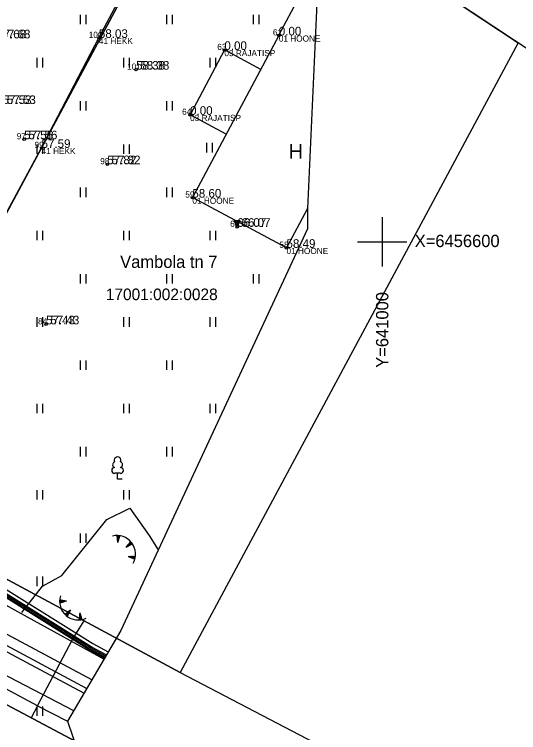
# Model space of a CAD drawing. Extents: x 640891 to 641083, y 6456526 to 6456669.
# Drawn here: x 640970.2 to 641011.1, y 6456560.3 to 6456618.4 of the extents above; entities that cross this region are included whole.
import ezdxf

# ---------------------------------------------------------------- set-up
doc = ezdxf.new("R2010")
doc.units = 0
for name, color, linetype in [('100koma2', 7, 'Continuous'), ('HALJASTUS', 7, 'Continuous'), ('HOONE', 7, 'Continuous'), ('KORGUS', 7, 'Continuous'), ('KPKAABEL', 7, 'Continuous'), ('KTRASS', 7, 'Continuous'), ('MOOTKORG', 7, 'Continuous'), ('MOOTKORG_MUU', 7, 'Continuous'), ('MOOTMPUNKT', 7, 'Continuous'), ('MOOTNR', 7, 'Continuous'), ('MOOTPIIR', 7, 'Continuous'), ('MPKAABEL', 7, 'Continuous'), ('PIIR', 7, 'Continuous'), ('PUU', 7, 'Continuous'), ('RELJEEF', 7, 'Continuous'), ('SITRASS', 7, 'Continuous'), ('SKTRASS', 7, 'Continuous'), ('TEE', 7, 'Continuous'), ('VORK', 7, 'Continuous'), ('VTRASS', 7, 'Continuous')]:
    doc.layers.add(name, color=color, linetype=linetype)

msp = doc.modelspace()

# ---------------------------------------------------------------- linework, layer by layer
at = {"layer": 'HALJASTUS'}
for p, q in [((640975.545, 6456618.381), (640975.545, 6456617.619)), ((640976, 6456618.381), (640976, 6456617.619)), ((640982.545, 6456618.381), (640982.545, 6456617.619)), ((640983, 6456618.381), (640983, 6456617.619)), ((640989.545, 6456618.381), (640989.545, 6456617.619)), ((640990, 6456618.381), (640990, 6456617.619)), ((640972.045, 6456614.881), (640972.045, 6456614.119)), ((640972.5, 6456614.881), (640972.5, 6456614.119)), ((640979.045, 6456614.881), (640979.045, 6456614.119)), ((640979.5, 6456614.881), (640979.5, 6456614.119)), ((640986.045, 6456614.881), (640986.045, 6456614.119)), ((640986.5, 6456614.881), (640986.5, 6456614.119)), ((640975.545, 6456611.381), (640975.545, 6456610.619)), ((640976, 6456611.381), (640976, 6456610.619)), ((640982.545, 6456611.381), (640982.545, 6456610.619)), ((640983, 6456611.381), (640983, 6456610.619)), ((640972.045, 6456607.881), (640972.045, 6456607.119)), ((640972.5, 6456607.881), (640972.5, 6456607.119)), ((640979.045, 6456607.881), (640979.045, 6456607.119)), ((640979.5, 6456607.881), (640979.5, 6456607.119)), ((640985.78, 6456607.996), (640985.78, 6456607.235)), ((640986.236, 6456607.996), (640986.236, 6456607.235)), ((640975.545, 6456604.381), (640975.545, 6456603.619)), ((640976, 6456604.381), (640976, 6456603.619)), ((640982.545, 6456604.381), (640982.545, 6456603.619)), ((640983, 6456604.381), (640983, 6456603.619)), ((640972.045, 6456600.881), (640972.045, 6456600.119)), ((640972.5, 6456600.881), (640972.5, 6456600.119)), ((640979.045, 6456600.881), (640979.045, 6456600.119)), ((640979.5, 6456600.881), (640979.5, 6456600.119)), ((640986.045, 6456600.881), (640986.045, 6456600.119)), ((640986.5, 6456600.881), (640986.5, 6456600.119)), ((640975.545, 6456597.381), (640975.545, 6456596.619)), ((640976, 6456597.381), (640976, 6456596.619)), ((640982.545, 6456597.381), (640982.545, 6456596.619)), ((640983, 6456597.381), (640983, 6456596.619)), ((640989.545, 6456597.381), (640989.545, 6456596.619)), ((640990, 6456597.381), (640990, 6456596.619)), ((640972.045, 6456593.881), (640972.045, 6456593.119)), ((640972.5, 6456593.881), (640972.5, 6456593.119)), ((640979.045, 6456593.881), (640979.045, 6456593.119)), ((640979.5, 6456593.881), (640979.5, 6456593.119)), ((640986.045, 6456593.881), (640986.045, 6456593.119)), ((640986.5, 6456593.881), (640986.5, 6456593.119)), ((640975.545, 6456590.381), (640975.545, 6456589.619)), ((640976, 6456590.381), (640976, 6456589.619)), ((640982.545, 6456590.381), (640982.545, 6456589.619)), ((640983, 6456590.381), (640983, 6456589.619)), ((640972.045, 6456586.881), (640972.045, 6456586.119)), ((640972.5, 6456586.881), (640972.5, 6456586.119)), ((640979.045, 6456586.881), (640979.045, 6456586.119)), ((640979.5, 6456586.881), (640979.5, 6456586.119)), ((640986.045, 6456586.881), (640986.045, 6456586.119)), ((640986.5, 6456586.881), (640986.5, 6456586.119)), ((640975.545, 6456583.381), (640975.545, 6456582.619)), ((640976, 6456583.381), (640976, 6456582.619)), ((640982.545, 6456583.381), (640982.545, 6456582.619)), ((640983, 6456583.381), (640983, 6456582.619)), ((640972.045, 6456579.881), (640972.045, 6456579.119)), ((640972.5, 6456579.881), (640972.5, 6456579.119)), ((640979.045, 6456579.881), (640979.045, 6456579.119)), ((640979.5, 6456579.881), (640979.5, 6456579.119)), ((640975.545, 6456576.381), (640975.545, 6456575.619)), ((640976, 6456576.381), (640976, 6456575.619)), ((640972.045, 6456572.881), (640972.045, 6456572.119)), ((640972.5, 6456572.881), (640972.5, 6456572.119)), ((640972.045, 6456562.381), (640972.045, 6456561.619)), ((640972.5, 6456562.381), (640972.5, 6456561.619))]:
    msp.add_line(p, q, dxfattribs=at)
for points in [[(640962.925, 6456576.62), (640957.383, 6456579.521), (640966.138, 6456596.056), (640972.417, 6456607.592), (640977.059, 6456616.501), (640985.041, 6456631.518)], [(640970.815, 6456569.988), (640972.5, 6456572.119), (640974.047, 6456572.963), (640977.712, 6456577.496), (640979.559, 6456578.42), (640981.117, 6456576.226), (640981.868, 6456575.042)]]:
    msp.add_lwpolyline(points, dxfattribs=at)
at = {"layer": 'HOONE'}
for p, q in [((640993.648, 6456620.522), (640991.616, 6456616.709)), ((640991.628, 6456616.702), (640984.629, 6456603.57)), ((640991.616, 6456616.709), (640991.628, 6456616.702)), ((640990.165, 6456613.956), (640987.221, 6456615.525)), ((640987.37, 6456608.714), (640984.444, 6456610.273)), ((640992.253, 6456599.507), (640984.629, 6456603.57)), ((640993.953, 6456602.696), (640992.253, 6456599.507))]:
    msp.add_line(p, q, dxfattribs=at)
msp.add_lwpolyline([(640987.221, 6456615.525), (640984.444, 6456610.273)], dxfattribs=at)
at = {"layer": 'KORGUS'}
for p, q in [((640988.261, 6456601.203), (640988.014, 6456601.69)), ((640988.507, 6456601.69), (640988.014, 6456601.69)), ((640988.042, 6456601.69), (640988.378, 6456601.435)), ((640988.083, 6456601.69), (640988.389, 6456601.457)), ((640988.125, 6456601.69), (640988.401, 6456601.48)), ((640988.166, 6456601.69), (640988.412, 6456601.503)), ((640988.207, 6456601.69), (640988.424, 6456601.525)), ((640988.248, 6456601.69), (640988.435, 6456601.548)), ((640988.261, 6456601.203), (640988.507, 6456601.69)), ((640988.29, 6456601.69), (640988.447, 6456601.571)), ((640988.331, 6456601.69), (640988.458, 6456601.593)), ((640988.372, 6456601.69), (640988.47, 6456601.616)), ((640988.413, 6456601.69), (640988.481, 6456601.639)), ((640988.455, 6456601.69), (640988.493, 6456601.661)), ((640988.496, 6456601.69), (640988.504, 6456601.684)), ((640988.023, 6456601.674), (640988.366, 6456601.412)), ((640988.049, 6456601.623), (640988.355, 6456601.389)), ((640988.074, 6456601.571), (640988.343, 6456601.367)), ((640988.1, 6456601.52), (640988.332, 6456601.344)), ((640988.126, 6456601.469), (640988.32, 6456601.321)), ((640988.152, 6456601.418), (640988.309, 6456601.299)), ((640988.178, 6456601.367), (640988.297, 6456601.276)), ((640988.204, 6456601.316), (640988.286, 6456601.253)), ((640988.23, 6456601.265), (640988.274, 6456601.23)), ((640988.256, 6456601.213), (640988.263, 6456601.208))]:
    msp.add_line(p, q, dxfattribs=at)
for centre in [(640980.07, 6456613.931), (640971.005, 6456608.294), (640977.739, 6456606.273), (640972.781, 6456593.308)]:
    msp.add_circle(centre, 0.1, dxfattribs=at)
at = {"layer": 'KPKAABEL'}
msp.add_lwpolyline([(640977.507, 6456566.281), (640976.27, 6456566.95), (640967.49, 6456572.43), (640959.27, 6456576.625), (640951.05, 6456580.82), (640939.86, 6456586.9), (640935.075, 6456589.63), (640930.29, 6456592.36), (640924.23, 6456595.65), (640919.26, 6456598.135), (640914.117, 6456600.706)], dxfattribs=at)
at = {"layer": 'KTRASS'}
msp.add_lwpolyline([(640976.059, 6456563.819), (640955.081, 6456575.091)], dxfattribs=at)
at = {"layer": 'MOOTMPUNKT'}
for centre in [(640977.059, 6456616.501), (640991.628, 6456616.702), (640987.221, 6456615.525), (640980.07, 6456613.931), (640984.444, 6456610.273), (640971.005, 6456608.294), (640972.417, 6456607.592), (640977.739, 6456606.273), (640984.629, 6456603.57), (640988.261, 6456601.203), (640992.252, 6456599.504), (640972.781, 6456593.308)]:
    msp.add_circle(centre, 0.1, dxfattribs=at)
at = {"layer": 'MOOTPIIR'}
msp.add_lwpolyline([(640994.744, 6456619.938), (640993.953, 6456602.696), (640993.953, 6456601.05), (640978.828, 6456568.525), (640974.506, 6456561.178), (640980.174, 6456544.523), (640977.11, 6456538.585), (640976.662, 6456538.007), (640959.29, 6456546.142)], dxfattribs=at)
at = {"layer": 'MPKAABEL'}
for points in [[(640914.173, 6456600.793), (640919.31, 6456598.225), (640924.28, 6456595.74), (640927.31, 6456594.095), (640930.34, 6456592.45), (640935.125, 6456589.72), (640939.91, 6456586.99), (640945.495, 6456583.945), (640951.08, 6456580.9), (640959.31, 6456576.71), (640967.54, 6456572.52), (640971.93, 6456569.78), (640976.32, 6456567.04), (640977.56, 6456566.369)], [(640977.608, 6456566.451), (640976.37, 6456567.12), (640971.98, 6456569.865), (640967.59, 6456572.61), (640959.355, 6456576.785), (640951.12, 6456580.96), (640945.54, 6456584.015), (640939.96, 6456587.07), (640935.175, 6456589.8), (640930.39, 6456592.53), (640927.355, 6456594.18), (640924.32, 6456595.83), (640919.35, 6456598.315), (640914.227, 6456600.876)], [(640977.66, 6456566.54), (640976.42, 6456567.21), (640972.03, 6456569.95), (640967.64, 6456572.69), (640959.395, 6456576.855), (640951.15, 6456581.02), (640945.58, 6456584.09), (640940.01, 6456587.16), (640935.225, 6456589.89), (640930.44, 6456592.62), (640927.405, 6456594.27), (640924.37, 6456595.92), (640919.4, 6456598.405), (640914.283, 6456600.963)], [(640957.06, 6456579.17), (640956.96, 6456578.31), (640962.37, 6456575.635), (640967.78, 6456572.96), (640976.57, 6456567.48), (640977.808, 6456566.792)]]:
    msp.add_lwpolyline(points, dxfattribs=at)
at = {"layer": 'PIIR'}
for points in [[(641029.209, 6456604.07), (641000.58, 6456623), (641039.59, 6456660.086)], [(640890.598, 6456615.08), (640904.36, 6456607.7), (640930.79, 6456593.51), (640957.22, 6456579.32), (640983.63, 6456565.13), (641002.905, 6456555.058)], [(640993.023, 6456550.09), (640989.66, 6456551.83), (640963.18, 6456565.91), (640936.74, 6456580.1), (640910.31, 6456594.28), (640890.598, 6456604.875)], [(640941.583, 6456525.865), (640963.18, 6456565.91), (640989.66, 6456551.83), (640975.643, 6456525.865)]]:
    msp.add_lwpolyline(points, dxfattribs=at)
for points in [[(640957.22, 6456579.32), (640930.79, 6456593.51), (640960.76, 6456649.34), (640985.89, 6456632.73)], [(640983.63, 6456565.13), (640957.22, 6456579.32), (640985.89, 6456632.73), (641000.58, 6456623), (641011.01, 6456616.1)]]:
    msp.add_lwpolyline(points, close=True, dxfattribs=at)
at = {"layer": 'PUU'}
for p, q in [((640978.811, 6456581.248), (640978.331, 6456581.248)), ((640978.571, 6456580.773), (640978.571, 6456581.248)), ((640978.951, 6456580.773), (640978.571, 6456580.773))]:
    msp.add_line(p, q, dxfattribs=at)
for centre, radius, start, end in [((640978.571, 6456582.293), 0.277, 332.5799, 207.4201), ((640978.401, 6456581.945), 0.233, 109.02174, 253.14154), ((640978.741, 6456581.945), 0.233, 286.85082, 70.98591), ((640978.334, 6456581.485), 0.238, 90.0016, 269.3953), ((640978.809, 6456581.485), 0.238, 270.6047, 89.9984)]:
    msp.add_arc(centre, radius, start, end, dxfattribs=at)
at = {"layer": 'RELJEEF'}
for p, q in [((640978.592, 6456575.65), (640978.533, 6456576.213)), ((640978.534, 6456576.203), (640978.685, 6456575.974)), ((640978.539, 6456576.149), (640978.676, 6456575.943)), ((640978.545, 6456576.095), (640978.667, 6456575.911)), ((640978.557, 6456576.213), (640978.694, 6456576.006)), ((640978.588, 6456576.211), (640978.703, 6456576.037)), ((640978.592, 6456575.65), (640978.749, 6456576.194)), ((640978.619, 6456576.209), (640978.713, 6456576.069)), ((640978.651, 6456576.207), (640978.722, 6456576.101)), ((640978.683, 6456576.203), (640978.731, 6456576.132)), ((640978.716, 6456576.199), (640978.74, 6456576.164)), ((640978.551, 6456576.042), (640978.658, 6456575.88)), ((640978.556, 6456575.988), (640978.649, 6456575.848)), ((640978.562, 6456575.934), (640978.64, 6456575.817)), ((640978.568, 6456575.88), (640978.631, 6456575.785)), ((640978.573, 6456575.827), (640978.622, 6456575.754)), ((640978.579, 6456575.773), (640978.613, 6456575.722)), ((640978.585, 6456575.719), (640978.604, 6456575.69)), ((640979.263, 6456575.281), (640979.637, 6456575.706)), ((640979.263, 6456575.281), (640979.77, 6456575.535)), ((640979.488, 6456575.536), (640979.448, 6456575.374)), ((640979.523, 6456575.577), (640979.477, 6456575.388)), ((640979.559, 6456575.617), (640979.507, 6456575.403)), ((640979.595, 6456575.658), (640979.536, 6456575.418)), ((640979.63, 6456575.699), (640979.565, 6456575.432)), ((640979.654, 6456575.688), (640979.595, 6456575.447)), ((640979.674, 6456575.664), (640979.624, 6456575.462)), ((640979.693, 6456575.64), (640979.653, 6456575.477)), ((640979.713, 6456575.615), (640979.683, 6456575.491)), ((640979.732, 6456575.589), (640979.712, 6456575.506)), ((640979.751, 6456575.562), (640979.741, 6456575.521)), ((640979.309, 6456575.334), (640979.301, 6456575.3)), ((640979.345, 6456575.374), (640979.33, 6456575.315)), ((640979.381, 6456575.415), (640979.36, 6456575.329)), ((640979.416, 6456575.455), (640979.389, 6456575.344)), ((640979.452, 6456575.496), (640979.419, 6456575.359)), ((640979.441, 6456574.508), (640979.964, 6456574.29)), ((640979.441, 6456574.508), (640980.008, 6456574.502)), ((640979.511, 6456574.507), (640979.48, 6456574.492)), ((640979.565, 6456574.507), (640979.511, 6456574.479)), ((640979.619, 6456574.506), (640979.541, 6456574.467)), ((640979.673, 6456574.506), (640979.571, 6456574.454)), ((640979.727, 6456574.505), (640979.602, 6456574.441)), ((640979.781, 6456574.504), (640979.632, 6456574.429)), ((640979.835, 6456574.504), (640979.662, 6456574.416)), ((640979.889, 6456574.503), (640979.692, 6456574.403)), ((640979.943, 6456574.503), (640979.723, 6456574.391)), ((640979.997, 6456574.502), (640979.753, 6456574.378)), ((640980.004, 6456574.477), (640979.783, 6456574.365)), ((640980, 6456574.447), (640979.814, 6456574.353)), ((640979.994, 6456574.416), (640979.844, 6456574.34)), ((640979.988, 6456574.385), (640979.874, 6456574.327)), ((640979.981, 6456574.353), (640979.904, 6456574.315)), ((640979.973, 6456574.321), (640979.935, 6456574.302)), ((640973.877, 6456570.894), (640973.977, 6456570.973)), ((640973.877, 6456570.862), (640974.009, 6456570.967)), ((640973.878, 6456570.926), (640973.945, 6456570.98)), ((640973.878, 6456570.831), (640974.041, 6456570.961)), ((640973.879, 6456570.959), (640973.912, 6456570.986)), ((640973.88, 6456570.8), (640974.073, 6456570.955)), ((640974.438, 6456570.884), (640973.881, 6456570.992)), ((640974.438, 6456570.884), (640973.881, 6456570.775)), ((640973.892, 6456570.777), (640974.106, 6456570.948)), ((640973.945, 6456570.788), (640974.138, 6456570.942)), ((640973.998, 6456570.798), (640974.17, 6456570.936)), ((640974.051, 6456570.808), (640974.202, 6456570.93)), ((640974.104, 6456570.819), (640974.235, 6456570.924)), ((640974.157, 6456570.829), (640974.267, 6456570.917)), ((640974.21, 6456570.84), (640974.299, 6456570.911)), ((640974.263, 6456570.85), (640974.331, 6456570.905)), ((640974.316, 6456570.86), (640974.363, 6456570.899)), ((640974.369, 6456570.871), (640974.396, 6456570.892)), ((640974.769, 6456570.164), (640974.325, 6456569.812)), ((640974.349, 6456569.789), (640974.35, 6456569.832)), ((640974.373, 6456569.767), (640974.376, 6456569.852)), ((640974.397, 6456569.745), (640974.402, 6456569.873)), ((640974.421, 6456569.725), (640974.427, 6456569.893)), ((640974.446, 6456569.705), (640974.453, 6456569.914)), ((640974.47, 6456569.686), (640974.479, 6456569.934)), ((640974.769, 6456570.164), (640974.49, 6456569.671)), ((640974.495, 6456569.68), (640974.504, 6456569.954)), ((640974.522, 6456569.727), (640974.53, 6456569.975)), ((640974.548, 6456569.774), (640974.556, 6456569.995)), ((640974.575, 6456569.821), (640974.582, 6456570.015)), ((640974.602, 6456569.868), (640974.607, 6456570.036)), ((640974.628, 6456569.915), (640974.633, 6456570.056)), ((640974.655, 6456569.962), (640974.659, 6456570.077)), ((640974.682, 6456570.009), (640974.685, 6456570.097)), ((640974.708, 6456570.056), (640974.71, 6456570.117)), ((640974.735, 6456570.103), (640974.736, 6456570.138)), ((640975.502, 6456569.94), (640975.459, 6456569.375)), ((640975.622, 6456569.565), (640975.484, 6456569.701)), ((640975.605, 6456569.616), (640975.486, 6456569.734)), ((640975.589, 6456569.668), (640975.489, 6456569.767)), ((640975.572, 6456569.719), (640975.491, 6456569.799)), ((640975.556, 6456569.771), (640975.494, 6456569.832)), ((640975.54, 6456569.822), (640975.496, 6456569.865)), ((640975.523, 6456569.873), (640975.498, 6456569.898)), ((640975.502, 6456569.94), (640975.674, 6456569.4)), ((640975.492, 6456569.377), (640975.462, 6456569.407)), ((640975.525, 6456569.379), (640975.464, 6456569.439)), ((640975.557, 6456569.383), (640975.467, 6456569.472)), ((640975.589, 6456569.386), (640975.469, 6456569.505)), ((640975.62, 6456569.391), (640975.472, 6456569.538)), ((640975.65, 6456569.396), (640975.474, 6456569.57)), ((640975.671, 6456569.41), (640975.476, 6456569.603)), ((640975.655, 6456569.462), (640975.479, 6456569.636)), ((640975.638, 6456569.513), (640975.481, 6456569.669))]:
    msp.add_line(p, q, dxfattribs=at)
for centre, start, end in [((640978.507, 6456574.7), 331.66138, 103.41249), ((640975.391, 6456570.887), 163.42341, 295.17451)]:
    msp.add_arc(centre, 1.514, start, end, dxfattribs=at)
at = {"layer": 'SITRASS'}
for points in [[(640972.09, 6456562.42), (640955.26, 6456571.44), (640948.66, 6456575.39), (640939.25, 6456580.69), (640930.23, 6456585.64), (640921.93, 6456589.97), (640913.28, 6456594.36)], [(640972.09, 6456562.42), (640974.91, 6456567.8), (640975.87, 6456569.3)], [(640972.09, 6456562.42), (640971.58, 6456561.44)], [(640972.09, 6456562.42), (640974.506, 6456561.178)]]:
    msp.add_lwpolyline(points, dxfattribs=at)
at = {"layer": 'SKTRASS'}
msp.add_lwpolyline([(640975.84, 6456563.446), (640963.035, 6456570.289), (640950.405, 6456577.04), (640931.282, 6456587.261), (640918.683, 6456593.994), (640912.062, 6456597.533)], dxfattribs=at)
at = {"layer": 'TEE'}
for points in [[(640977.461, 6456566.201), (640971.27, 6456569.61), (640958.74, 6456576.51), (640944.02, 6456584.555), (640929.3, 6456592.6), (640917.98, 6456598.615), (640914.098, 6456600.678)], [(640911.131, 6456596.096), (640915.765, 6456593.725), (640927.19, 6456587.88), (640941.825, 6456579.785), (640956.46, 6456571.69), (640969.135, 6456565.09), (640975.008, 6456562.032)]]:
    msp.add_lwpolyline(points, dxfattribs=at)
at = {"layer": 'VORK'}
for p, q in [((641000, 6456602), (641000, 6456598)), ((640998, 6456600), (641002, 6456600))]:
    msp.add_line(p, q, dxfattribs=at)
at = {"layer": 'VTRASS'}
msp.add_lwpolyline([(640976.477, 6456564.528), (640953.923, 6456576.584)], dxfattribs=at)

# ---------------------------------------------------------------- texts
at = {"layer": '100koma2'}
for s, p in [('41 HEKK', (640977.059, 6456616.001)), ('01 HOONE', (640991.628, 6456616.202)), ('03 RAJATISP', (640987.221, 6456615.025)), ('03 RAJATISP', (640984.444, 6456609.773)), ('41 HEKK', (640972.417, 6456607.092)), ('01 HOONE', (640984.629, 6456603.07)), ('01 HOONE', (640992.252, 6456599.004))]:
    msp.add_text(s, height=0.5, dxfattribs=at).set_placement(p)
at = {"layer": 'HOONE'}
msp.add_text('H', height=1.2, dxfattribs=at).set_placement((640992.427, 6456606.713))
at = {"layer": 'KORGUS'}
for s, p in [('57.68', (640969.168, 6456616.461)), ('58.38', (640980.42, 6456613.931)), ('57.53', (640969.608, 6456611.148)), ('57.56', (640971.355, 6456608.294)), ('57.82', (640978.089, 6456606.273)), ('66.07', (640988.611, 6456601.203)), ('57.43', (640973.131, 6456593.308))]:
    msp.add_text(s, height=0.7, dxfattribs=at).set_placement(p)
at = {"layer": 'MOOTKORG'}
for s, p in [('0.00', (640991.628, 6456616.702)), ('57.68', (640968.818, 6456616.461)), ('58.03', (640977.059, 6456616.501)), ('0.00', (640987.221, 6456615.525)), ('58.38', (640980.07, 6456613.931)), ('57.53', (640969.258, 6456611.148)), ('0.00', (640984.444, 6456610.273)), ('57.56', (640971.005, 6456608.294)), ('57.59', (640972.417, 6456607.592)), ('57.82', (640977.739, 6456606.273)), ('58.60', (640984.629, 6456603.57)), ('58.49', (640992.252, 6456599.504)), ('57.43', (640972.781, 6456593.308))]:
    msp.add_text(s, height=0.7, dxfattribs=at).set_placement(p)
at = {"layer": 'MOOTKORG_MUU'}
msp.add_text('66.07', height=0.7, dxfattribs=at).set_placement((640988.261, 6456601.203))
at = {"layer": 'MOOTNR'}
for s, p in [('100', (640976.234, 6456616.501)), ('61', (640991.153, 6456616.702)), ('63', (640986.646, 6456615.525)), ('101', (640979.345, 6456613.931)), ('64', (640983.794, 6456610.273)), ('97', (640970.405, 6456608.294)), ('99', (640971.843, 6456607.592)), ('98', (640977.164, 6456606.273)), ('59', (640984.054, 6456603.57)), ('60', (640987.686, 6456601.203)), ('58', (640991.677, 6456599.504)), ('84', (640972.132, 6456593.308))]:
    msp.add_text(s, height=0.5, dxfattribs=at).set_placement(p)
at = {"layer": 'PIIR'}
for s, height, p in [('Vambola tn 7', 1.00002, (640978.78, 6456597.88)), ('17001:002:0028', 0.9375, (640977.615, 6456595.27))]:
    msp.add_text(s, height=height, dxfattribs=at).set_placement(p)
at = {"layer": 'VORK'}
msp.add_text('X=6456600     ', height=1, dxfattribs=at).set_placement((641002.633, 6456599.567))
msp.add_text('Y=641000     ', height=1, rotation=90, dxfattribs=at).set_placement((641000.5, 6456589.79))

doc.saveas('drawing.dxf')
